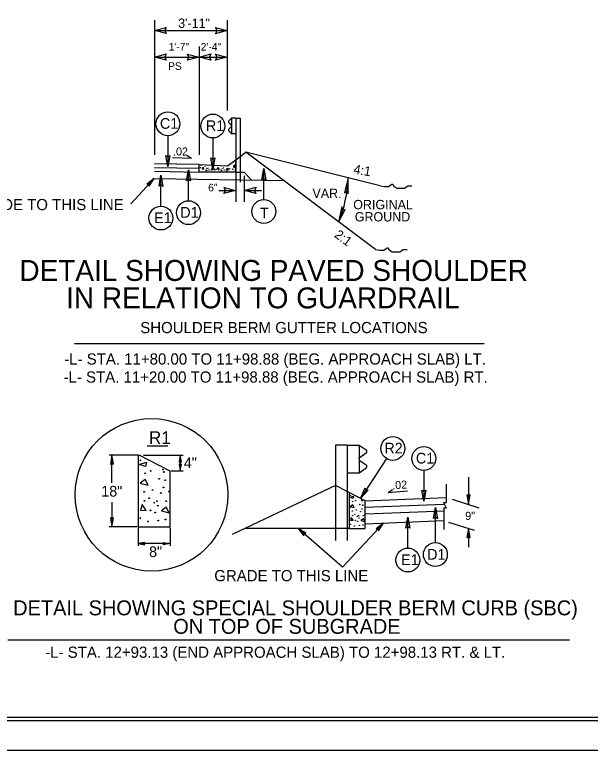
# Model space of a CAD drawing. Extents: x 574067 to 574470, y -53282 to -53062.
# Drawn here: x 574110.3 to 574197, y -53282.1 to -53171.2 of the extents above; entities that cross this region are included whole.
import ezdxf

# ---------------------------------------------------------------- set-up
doc = ezdxf.new("R2010")
doc.units = 0
for name, color, linetype in [('Old_Level_1', 7, 'Continuous'), ('Old_Level_11', 7, 'Continuous'), ('Old_Level_60', 7, 'Continuous'), ('Prop Dimension', 7, 'Continuous'), ('Prop Dimension Text', 7, 'Continuous'), ('Prop Terminator CELL', 7, 'Continuous'), ('Sheet Cutting Line CELL', 7, 'Continuous'), ('Sheet Plot Border Inside CELL', 7, 'Continuous'), ('Sheet Plot Border Outside CELL', 7, 'Continuous'), ('Sheet Typical CELL', 7, 'Continuous'), ('Typical Berm CELL', 7, 'Continuous'), ('Typical Curb CELL', 7, 'Continuous'), ('Typical Detail Wedge2 CELL', 7, 'Continuous'), ('Typical Guardrail CELL', 7, 'Continuous'), ('Typical Hinge Slope Arterial CELL', 7, 'Continuous'), ('Typical Hinge Slope Interstate CELL', 7, 'Continuous'), ('Typical ID Circle CELL', 7, 'Continuous'), ('Typical Pavement Slope CELL', 7, 'Continuous'), ('Typical Pavement Slope Information CELL', 7, 'Continuous'), ('Typical Terminator CELL', 7, 'Continuous'), ('Typical Text General CELL', 7, 'Continuous'), ('Typical Text Grade Point CELL', 7, 'Continuous'), ('Typical Text ID Circle CELL', 7, 'Continuous'), ('Typical Text Label CELL', 7, 'Continuous')]:
    doc.layers.add(name, color=color, linetype=linetype)

msp = doc.modelspace()

# ---------------------------------------------------------------- linework, layer by layer
at = {"layer": 'Old_Level_1'}
msp.add_line((574119.32, -53220.8), (574181.04, -53220.8), dxfattribs=at)
at = {"layer": 'Old_Level_11'}
for points in [[(574130.59, -53197.05), (574131.35, -53195.89), (574130.23, -53196.73), (574130.53, -53196.77)], [(574125.21, -53239), (574124.96, -53237.64), (574124.73, -53239.01), (574124.97, -53238.83)], [(574135.45, -53238.66), (574135.27, -53237.64), (574135.09, -53238.66), (574135.28, -53238.53)], [(574135.1, -53238.96), (574135.27, -53239.98), (574135.46, -53238.96), (574135.28, -53239.08)], [(574178.47, -53243.62), (574178.69, -53244.99), (574178.95, -53243.62), (574178.71, -53243.79)], [(574124.74, -53247.07), (574124.96, -53248.44), (574125.22, -53247.07), (574124.98, -53247.24)], [(574165.11, -53249.03), (574165.87, -53247.87), (574164.76, -53248.71), (574165.06, -53248.75)], [(574154.2, -53249.4), (574153.02, -53248.69), (574153.89, -53249.77), (574153.92, -53249.47)], [(574178.94, -53250.03), (574178.69, -53248.67), (574178.46, -53250.04), (574178.7, -53249.87)], [(574129.94, -53250.77), (574128.92, -53250.95), (574129.94, -53251.13), (574129.81, -53250.95)], [(574132.69, -53250.77), (574133.72, -53250.95), (574132.69, -53251.13), (574132.82, -53250.95)]]:
    msp.add_lwpolyline(points, close=True, dxfattribs=at)
at = {"layer": 'Prop Dimension'}
for p, q in [((574131.38, -53172), (574131.38, -53181.04)), ((574142.35, -53172), (574142.35, -53181.04)), ((574131.38, -53173.59), (574142.35, -53173.59)), ((574138.11, -53176.01), (574138.11, -53181.04)), ((574131.38, -53177.58), (574138.11, -53177.58)), ((574138.11, -53177.58), (574142.35, -53177.58)), ((574131.38, -53181.04), (574131.38, -53192.34)), ((574138.11, -53181.04), (574138.11, -53192.34)), ((574142.35, -53181.04), (574142.35, -53185.64)), ((574127.79, -53199.71), (574131.35, -53195.89)), ((574143.63, -53195.51), (574143.63, -53199.42)), ((574144.9, -53195.51), (574144.9, -53199.42)), ((574141.07, -53197.69), (574143.63, -53197.69)), ((574144.9, -53197.69), (574147.5, -53197.69)), ((574128.9, -53237.64), (574124.55, -53237.64)), ((574124.96, -53241.8), (574124.96, -53237.64)), ((574129.7, -53237.64), (574135.68, -53237.64)), ((574135.27, -53237.64), (574135.27, -53239.98)), ((574135.68, -53240.04), (574133.89, -53240.04)), ((574178.69, -53240.96), (574178.69, -53244.99)), ((574124.96, -53244.69), (574124.96, -53248.44)), ((574176.21, -53244.26), (574180.27, -53245.55)), ((574128.75, -53248.44), (574124.55, -53248.44)), ((574159.71, -53254.5), (574165.87, -53247.87)), ((574175.69, -53247.72), (574179.57, -53248.95)), ((574128.92, -53248.6), (574128.92, -53251.27)), ((574133.72, -53248.6), (574133.72, -53251.27)), ((574159.71, -53254.5), (574153.02, -53248.69)), ((574178.69, -53248.67), (574178.69, -53251.5)), ((574133.72, -53250.95), (574128.92, -53250.95))]:
    msp.add_line(p, q, dxfattribs=at)
msp.add_circle((574130.93, -53243.6), 11.5, dxfattribs=at)
at = {"layer": 'Prop Terminator CELL'}
for points in [[(574133.15, -53174.04), (574131.38, -53173.59), (574133.16, -53173.11), (574132.94, -53173.59)], [(574140.58, -53173.13), (574142.35, -53173.59), (574140.57, -53174.06), (574140.8, -53173.59)], [(574133.15, -53178.04), (574131.38, -53177.58), (574133.16, -53177.11), (574132.94, -53177.58)], [(574136.34, -53177.13), (574138.11, -53177.58), (574136.33, -53178.06), (574136.56, -53177.58)], [(574139.89, -53178.04), (574138.11, -53177.58), (574139.89, -53177.11), (574139.67, -53177.58)], [(574140.58, -53177.13), (574142.35, -53177.58), (574140.57, -53178.06), (574140.8, -53177.58)], [(574141.86, -53197.23), (574143.63, -53197.69), (574141.85, -53198.17), (574142.08, -53197.69)], [(574146.67, -53198.15), (574144.9, -53197.69), (574146.68, -53197.22), (574146.46, -53197.69)]]:
    msp.add_lwpolyline(points, close=True, dxfattribs=at)
at = {"layer": 'Sheet Cutting Line CELL'}
msp.add_line((574066.93, -53282.12), (574403.73, -53282.12), dxfattribs=at)
at = {"layer": 'Sheet Plot Border Inside CELL'}
msp.add_lwpolyline([(574402.83, -53066.61), (574069.53, -53066.61), (574069.53, -53277.63), (574402.83, -53277.63)], close=True, dxfattribs=at)
at = {"layer": 'Sheet Plot Border Outside CELL'}
msp.add_lwpolyline([(574403.73, -53062.12), (574066.93, -53062.12), (574066.93, -53282.12), (574403.73, -53282.12)], close=True, dxfattribs=at)
at = {"layer": 'Sheet Typical CELL'}
msp.add_lwpolyline([(574400.33, -53067.12), (574100.33, -53067.12), (574100.33, -53277.12), (574400.33, -53277.12)], close=True, dxfattribs=at)
at = {"layer": 'Typical Berm CELL'}
msp.add_line((574146.01, -53196.14), (574144.9, -53194.94), dxfattribs=at)
at = {"layer": 'Typical Curb CELL'}
for p, q in [((574142.38, -53194.01), (574143.63, -53193.07)), ((574143.63, -53194.92), (574143.63, -53193.07)), ((574138.11, -53193.78), (574138.11, -53193.78)), ((574138.11, -53194.92), (574138.11, -53193.81)), ((574138.13, -53193.78), (574142.38, -53194.01)), ((574138.55, -53194.51), (574138.71, -53194.18)), ((574138.71, -53194.18), (574138.77, -53194.49)), ((574140.83, -53194.51), (574140.99, -53194.18)), ((574140.99, -53194.18), (574141.05, -53194.49)), ((574143.29, -53193.98), (574143.32, -53194.23)), ((574143.57, -53194.1), (574143.29, -53193.98)), ((574143.32, -53194.23), (574143.57, -53194.1)), ((574143.63, -53194.92), (574138.11, -53194.92)), ((574138.77, -53194.49), (574138.55, -53194.51)), ((574139.95, -53194.65), (574140.06, -53194.33)), ((574140.25, -53194.54), (574139.95, -53194.65)), ((574140.06, -53194.33), (574140.25, -53194.54)), ((574141.05, -53194.49), (574140.83, -53194.51)), ((574142.23, -53194.65), (574142.34, -53194.33)), ((574142.53, -53194.54), (574142.23, -53194.65)), ((574142.34, -53194.33), (574142.53, -53194.54)), ((574128.92, -53237.79), (574129.07, -53237.64)), ((574128.92, -53237.79), (574128.92, -53248.44)), ((574133.72, -53240.04), (574129.07, -53237.64)), ((574129.05, -53239.01), (574130.16, -53238.69)), ((574130.04, -53239.34), (574129.05, -53239.01)), ((574130.16, -53238.69), (574130.04, -53239.34)), ((574133.72, -53248.44), (574133.72, -53240.04)), ((574129.95, -53241.3), (574129.21, -53241.84)), ((574129.21, -53241.84), (574130.4, -53242.13)), ((574130.4, -53242.13), (574129.95, -53241.3)), ((574163.13, -53244.49), (574160.43, -53243.09)), ((574160.73, -53243.36), (574160.81, -53243.29)), ((574160.73, -53243.36), (574160.73, -53248.69)), ((574160.8, -53243.97), (574161.35, -53243.81)), ((574161.29, -53244.14), (574160.8, -53243.97)), ((574161.35, -53243.81), (574161.29, -53244.14)), ((574129.5, -53245.08), (574129.25, -53245.89)), ((574130.12, -53245.94), (574129.5, -53245.08)), ((574161.25, -53245.12), (574160.88, -53245.39)), ((574161.48, -53245.53), (574161.25, -53245.12)), ((574163.13, -53248.69), (574163.13, -53244.49)), ((574129.25, -53245.89), (574130.12, -53245.94)), ((574133.15, -53245.48), (574132.41, -53246.02)), ((574132.41, -53246.02), (574133.6, -53246.31)), ((574133.6, -53246.31), (574133.15, -53245.48)), ((574160.88, -53245.39), (574161.48, -53245.53)), ((574161.02, -53247.01), (574160.9, -53247.41)), ((574160.9, -53247.41), (574161.33, -53247.44)), ((574161.33, -53247.44), (574161.02, -53247.01)), ((574162.85, -53247.21), (574162.48, -53247.48)), ((574163.08, -53247.62), (574162.85, -53247.21)), ((574128.92, -53248.44), (574133.72, -53248.44)), ((574162.48, -53247.48), (574163.08, -53247.62)), ((574160.73, -53248.69), (574163.13, -53248.69))]:
    msp.add_line(p, q, dxfattribs=at)
for centre, radius in [((574129.25, -53238.39), 0.0577), ((574129.95, -53240.36), 0.0577), ((574130.81, -53240), 0.0577), ((574132.66, -53239.79), 0.0577), ((574132.78, -53240.15), 0.0577), ((574132.09, -53241.18), 0.0577), ((574132.99, -53241.39), 0.0577), ((574131.06, -53242.87), 0.0577), ((574132.74, -53242.5), 0.0577), ((574129.83, -53243.15), 0.0577), ((574130.57, -53244.11), 0.0577), ((574132.33, -53243.32), 0.0577), ((574133.57, -53243.11), 0.0577), ((574160.9, -53243.66), 0.0289), ((574129.87, -53244.5), 0.0577), ((574131.35, -53244.78), 0.0577), ((574131.75, -53244.54), 0.0577), ((574131.88, -53245.24), 0.0577), ((574133.15, -53244.54), 0.0577), ((574161.25, -53244.65), 0.0289), ((574161.68, -53244.47), 0.0289), ((574162.32, -53245.06), 0.0289), ((574162.61, -53244.36), 0.0289), ((574162.67, -53244.54), 0.0289), ((574162.77, -53245.16), 0.0289), ((574130.77, -53245.94), 0.0577), ((574131.47, -53246.26), 0.0577), ((574161.19, -53246.04), 0.0289), ((574161.8, -53245.9), 0.0289), ((574162.44, -53246.13), 0.0289), ((574162.65, -53245.72), 0.0289), ((574163.06, -53246.02), 0.0289), ((574129.25, -53247.13), 0.0577), ((574131.92, -53247.46), 0.0577), ((574133.03, -53247.33), 0.0577), ((574161.21, -53246.72), 0.0289), ((574161.56, -53246.52), 0.0289), ((574161.66, -53247.44), 0.0289), ((574161.95, -53246.86), 0.0289), ((574162.15, -53246.74), 0.0289), ((574162.21, -53247.09), 0.0289), ((574162.85, -53246.74), 0.0289), ((574130.4, -53247.62), 0.0577), ((574160.9, -53248.03), 0.0289), ((574161.48, -53248.28), 0.0289), ((574162.01, -53247.6), 0.0289), ((574162.23, -53248.2), 0.0289), ((574162.79, -53248.13), 0.0289)]:
    msp.add_circle(centre, radius, dxfattribs=at)
msp.add_ellipse((574138.13, -53193.81), major_axis=(0, -0.0286), ratio=0.666667, start_param=3.105848, end_param=4.712389, dxfattribs=at)
for centre in [(574138.35, -53193.92), (574139.02, -53194.13), (574143.52, -53193.87), (574138.28, -53194.27), (574139.13, -53194.62), (574139.23, -53194.71), (574139.29, -53194.36), (574139.43, -53194.37), (574139.52, -53194.29), (574139.6, -53194.6), (574139.96, -53194.5), (574140.34, -53194.54), (574140.37, -53194.4), (574140.38, -53194.24), (574140.49, -53194.63), (574140.66, -53194.51), (574140.84, -53194.48), (574141.06, -53194.62), (574141.41, -53194.62), (574141.51, -53194.71), (574141.57, -53194.36), (574141.8, -53194.29), (574141.89, -53194.6), (574142.24, -53194.5), (574142.29, -53194.77), (574142.62, -53194.54), (574142.65, -53194.4), (574143.12, -53194.48), (574143.34, -53194.62)]:
    msp.add_ellipse(centre, major_axis=(0, 0.022), ratio=0.666667, dxfattribs=at)
at = {"layer": 'Typical Guardrail CELL'}
for p, q in [((574142.96, -53186.8), (574142.58, -53187.21)), ((574142.96, -53187.87), (574142.58, -53187.46)), ((574143.63, -53186.8), (574142.96, -53186.8)), ((574142.96, -53186.8), (574142.96, -53189.14)), ((574143.63, -53186.8), (574143.63, -53193.07)), ((574143.63, -53186.8), (574144.3, -53186.8)), ((574144.3, -53186.8), (574144.3, -53192.57)), ((574142.96, -53188.06), (574142.58, -53188.47)), ((574142.96, -53187.97), (574142.96, -53187.87)), ((574142.96, -53187.97), (574142.96, -53188.06)), ((574142.96, -53189.14), (574142.58, -53188.73)), ((574143.63, -53189.14), (574142.96, -53189.14)), ((574143.63, -53193.07), (574143.63, -53196.43)), ((574144.3, -53192.57), (574144.3, -53196.43)), ((574160.43, -53236.1), (574158.64, -53236.1)), ((574158.64, -53236.1), (574158.64, -53248.69)), ((574160.43, -53236.1), (574160.43, -53248.69)), ((574160.43, -53236.1), (574162.22, -53236.1)), ((574162.22, -53236.1), (574162.22, -53240.27)), ((574162.22, -53236.1), (574163.26, -53236.83)), ((574162.22, -53238.02), (574163.26, -53237.29)), ((574162.22, -53238.19), (574162.22, -53238.02)), ((574162.22, -53238.19), (574162.22, -53238.35)), ((574162.22, -53238.35), (574163.26, -53239.08)), ((574162.22, -53240.27), (574163.26, -53239.54)), ((574160.43, -53240.27), (574162.22, -53240.27)), ((574158.64, -53248.69), (574158.64, -53250.49)), ((574160.43, -53248.69), (574160.43, -53250.49))]:
    msp.add_line(p, q, dxfattribs=at)
for centre, start, end in [((574163.11, -53237.06), 304.9888, 54.997), ((574163.11, -53239.31), 304.9634, 54.9941)]:
    msp.add_arc(centre, 0.28, start, end, dxfattribs=at)
for centre, major_axis, start_param, end_param in [((574142.63, -53187.33), (0, -0.157), 3.75251, 5.672516), ((574142.64, -53188.6), (0, 0.157), 0.610968, 2.531366)]:
    msp.add_ellipse(centre, major_axis=major_axis, ratio=0.666667, start_param=start_param, end_param=end_param, dxfattribs=at)
at = {"layer": 'Typical Hinge Slope Arterial CELL'}
for p, q in [((574164.7, -53206.59), (574145.15, -53191.93)), ((574165.39, -53196.99), (574145.15, -53191.93)), ((574138.11, -53193.78), (574131.38, -53193.67)), ((574131.37, -53194.22), (574138.1, -53194.34)), ((574131.38, -53194.81), (574138.11, -53194.92)), ((574143.63, -53194.92), (574144.9, -53194.94)), ((574131.35, -53195.89), (574150.87, -53196.22))]:
    msp.add_line(p, q, dxfattribs=at)
for points in [[(574165.39, -53196.99), (574166.06, -53197.12), (574166.23, -53197.12), (574166.48, -53197.12), (574166.64, -53197.12), (574166.81, -53196.99), (574166.97, -53196.87), (574167.14, -53196.74), (574167.31, -53196.74), (574167.39, -53196.99), (574167.56, -53197.12), (574167.72, -53197.24), (574167.89, -53197.37), (574168.06, -53197.37), (574168.22, -53197.37), (574168.39, -53197.37), (574168.55, -53197.37), (574168.72, -53197.37), (574168.89, -53197.37), (574169.05, -53197.37), (574169.22, -53197.24), (574169.39, -53197.12), (574169.55, -53196.99), (574169.8, -53196.99), (574169.97, -53196.99), (574170.14, -53196.99)], [(574164.7, -53206.59), (574165.36, -53206.72), (574165.53, -53206.72), (574165.78, -53206.72), (574165.95, -53206.72), (574166.11, -53206.59), (574166.28, -53206.47), (574166.44, -53206.34), (574166.61, -53206.34), (574166.69, -53206.59), (574166.86, -53206.72), (574167.03, -53206.84), (574167.19, -53206.97), (574167.36, -53206.97), (574167.53, -53206.97), (574167.69, -53206.97), (574167.86, -53206.97), (574168.03, -53206.97), (574168.19, -53206.97), (574168.36, -53206.97), (574168.52, -53206.84), (574168.69, -53206.72), (574168.86, -53206.59), (574169.11, -53206.59), (574169.27, -53206.59), (574169.44, -53206.59)]]:
    msp.add_lwpolyline(points, dxfattribs=at)
msp.add_ellipse((574150.59, -53194.71), major_axis=(0, -15.01), ratio=0.666667, start_param=1.029417, end_param=1.499036, dxfattribs=at)
at = {"layer": 'Typical ID Circle CELL'}
for p, q in [((574133.4, -53189.44), (574133.4, -53194.1)), ((574140.17, -53189.78), (574140.17, -53194.44)), ((574136.5, -53199.25), (574136.5, -53194.59)), ((574147.85, -53199.07), (574147.85, -53194.41)), ((574132.35, -53200.06), (574132.35, -53195.4)), ((574166.32, -53238.12), (574162.44, -53244.13)), ((574171.97, -53239.92), (574171.97, -53244.58)), ((574173.7, -53250.81), (574173.7, -53245.52)), ((574169.55, -53251.62), (574169.55, -53246.96))]:
    msp.add_line(p, q, dxfattribs=at)
for centre in [(574133.4, -53187.64), (574140.17, -53187.98), (574136.5, -53201.05), (574147.85, -53200.88), (574132.35, -53201.86), (574167.29, -53236.6), (574171.97, -53238.12), (574169.55, -53253.43), (574173.7, -53252.61)]:
    msp.add_circle(centre, 1.8, dxfattribs=at)
at = {"layer": 'Typical Pavement Slope CELL'}
for p, q in [((574143.63, -53193.07), (574145.15, -53191.93)), ((574158.64, -53242.17), (574143.09, -53249.59)), ((574160.43, -53243.09), (574158.64, -53242.17)), ((574163.13, -53244.49), (574175.33, -53243.98)), ((574163.17, -53245.48), (574175.03, -53244.99)), ((574163.22, -53246.48), (574175, -53245.99)), ((574163.13, -53247.99), (574175, -53247.49))]:
    msp.add_line(p, q, dxfattribs=at)
at = {"layer": 'Typical Pavement Slope Information CELL'}
for p, q in [((574136.97, -53192.86), (574134.08, -53192.8)), ((574136.97, -53192.86), (574136.31, -53192.46)), ((574166.59, -53243.23), (574167.23, -53242.79)), ((574175.33, -53241.98), (574175.33, -53244.77)), ((574166.59, -53243.23), (574169.48, -53243.01)), ((574174.91, -53244.77), (574175.33, -53244.77)), ((574174.91, -53244.77), (574175.33, -53245.55)), ((574175, -53245.55), (574175.33, -53245.55)), ((574175, -53245.55), (574175, -53248.84)), ((574160.73, -53248.69), (574144.98, -53248.69))]:
    msp.add_line(p, q, dxfattribs=at)
at = {"layer": 'Typical Terminator CELL'}
for points in [[(574133.69, -53192.43), (574133.4, -53194.1), (574133.11, -53192.42), (574133.4, -53192.64)], [(574140.46, -53192.77), (574140.17, -53194.44), (574139.88, -53192.76), (574140.17, -53192.98)], [(574136.21, -53196.26), (574136.5, -53194.59), (574136.8, -53196.27), (574136.5, -53196.05)], [(574147.56, -53196.08), (574147.85, -53194.41), (574148.15, -53196.09), (574147.85, -53195.88)], [(574132.06, -53197.07), (574132.35, -53195.4), (574132.64, -53197.08), (574132.35, -53196.87)], [(574160.58, -53198.19), (574160.57, -53195.79), (574160.03, -53198.07), (574160.34, -53197.84)], [(574159.59, -53200.19), (574159.13, -53202.49), (574160.09, -53200.55), (574159.75, -53200.63)], [(574163.58, -53242.88), (574162.44, -53244.13), (574163.1, -53242.56), (574163.23, -53242.9)], [(574172.26, -53242.91), (574171.97, -53244.58), (574171.68, -53242.9), (574171.97, -53243.12)], [(574173.42, -53247.19), (574173.7, -53245.52), (574174, -53247.2), (574173.7, -53246.99)], [(574169.26, -53248.63), (574169.55, -53246.96), (574169.84, -53248.64), (574169.55, -53248.43)]]:
    msp.add_lwpolyline(points, close=True, dxfattribs=at)
at = {"layer": 'Typical Text General CELL'}
msp.add_line((574109.27, -53265.46), (574193.94, -53265.46), dxfattribs=at)
at = {"layer": 'Typical Text ID Circle CELL'}
msp.add_line((574130.25, -53236.19), (574133.38, -53236.19), dxfattribs=at)

# ---------------------------------------------------------------- texts
at = {"layer": 'Old_Level_1'}
for p in [(574103.54, -53200.67), (574140.39, -53256.63)]:
    msp.add_text('GRADE TO THIS LINE', height=1.6875, dxfattribs=at).set_placement(p)
at = {"layer": 'Old_Level_60'}
for s, p in [('SHOULDER BERM GUTTER LOCATIONS', (574129.23, -53219.22)), ('-L- STA. 11+80.00 TO 11+98.88 (BEG. APPROACH SLAB) LT.', (574117.77, -53223.96)), ('-L- STA. 11+20.00 TO 11+98.88 (BEG. APPROACH SLAB) RT.', (574117.67, -53226.68)), ('-L- STA. 12+93.13 (END APPROACH SLAB) TO 12+98.13 RT. & LT.', (574114.91, -53268.18))]:
    msp.add_text(s, height=1.6899, dxfattribs=at).set_placement(p)
at = {"layer": 'Prop Dimension Text'}
for s, height, p in [('3\'-11"', 1.406, (574134.95, -53173.18)), ('1\'-7"', 1.15, (574133.52, -53176.6)), ('2\'-4"', 1.15, (574138.35, -53176.61)), ('PS', 1.15, (574133.43, -53179.52)), ('.02', 1.217, (574134.17, -53192.43)), ('6"', 1.15, (574139.47, -53197.84))]:
    msp.add_text(s, height=height, dxfattribs=at).set_placement(p)
msp.add_text('.02', height=1.217, rotation=3.1932, dxfattribs=at).set_placement((574167.22, -53242.77))
at = {"layer": 'Typical Detail Wedge2 CELL'}
for s, p in [('4"', (574135.8, -53239.57)), ('18"', (574123.36, -53243.86)), ('8"', (574130.57, -53252.99))]:
    msp.add_text(s, height=1.611, dxfattribs=at).set_placement(p)
at = {"layer": 'Typical Hinge Slope Arterial CELL'}
for s, rotation, p in [('4:1', 350.5377, (574161.3, -53195.14)), ('VAR. ', 360, (574155.18, -53198.83)), ('2:1', 323.1301, (574158.37, -53204.63))]:
    msp.add_text(s, height=1.406, rotation=rotation, dxfattribs=at).set_placement(p)
at = {"layer": 'Typical Hinge Slope Interstate CELL'}
for s, p in [('ORIGINAL', (574161.33, -53200.53)), ('GROUND', (574161.56, -53202.37))]:
    msp.add_text(s, height=1.406, dxfattribs=at).set_placement(p)
at = {"layer": 'Typical Text Grade Point CELL'}
msp.add_text('9"', height=1.223, dxfattribs=at).set_placement((574178.19, -53247.38))
at = {"layer": 'Typical Text ID Circle CELL'}
for s, height, p in [('C1', 1.614, (574132.2, -53188.4)), ('R1', 1.614, (574139.13, -53188.74)), ('D1', 1.614, (574135.27, -53201.81)), ('T', 1.61, (574147.28, -53201.92)), ('E1', 1.614, (574131.33, -53202.62)), ('R1', 1.937, (574130.53, -53235.94)), ('R2', 1.614, (574166.02, -53237.36)), ('C1', 1.614, (574170.77, -53238.88)), ('D1', 1.614, (574172.47, -53253.38)), ('E1', 1.614, (574168.54, -53254.19))]:
    msp.add_text(s, height=height, dxfattribs=at).set_placement(p)
at = {"layer": 'Typical Text Label CELL'}
for s, height, p in [('DETAIL SHOWING PAVED SHOULDER', 3.1536, (574111.02, -53211.34)), ('IN RELATION TO GUARDRAIL', 3.1536, (574118.06, -53215.48)), ('DETAIL SHOWING SPECIAL SHOULDER BERM CURB (SBC)', 2.25, (574110.08, -53261.77)), ('ON TOP OF SUBGRADE', 2.25, (574134.2, -53264.56))]:
    msp.add_text(s, height=height, dxfattribs=at).set_placement(p)

doc.saveas('drawing.dxf')
